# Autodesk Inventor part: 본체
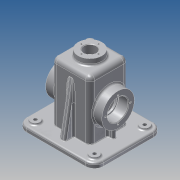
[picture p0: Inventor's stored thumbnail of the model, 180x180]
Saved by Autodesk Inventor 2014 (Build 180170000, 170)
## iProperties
Created: 2015-12
Part Number: 본체
Material: 알루미늄 6061
Document SubType Name: Modeling
Designer: Administrator
Density: 2.71 g/cm^3
Appearance: 알루미늄 - 평지
Mass: 957.91 g
Surface Area: 888.538 cm^2
Volume: 353.472 cm^3
Author: Administrator
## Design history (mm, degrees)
sketch "스케치1"
  geometry: L1 (-32.5, 32.5)-(32.5, 32.5); L2 (32.5, 32.5)-(32.5, -32.5); L3 (32.5, -32.5)-(-32.5, -32.5); L4 (-32.5, -32.5)-(-32.5, 32.5); 3 further points
  constraints: 8 end point, 2 midpoint, 2 parallel, 1 horizontal, 1 horizontal alignment, 1 perpendicular, 1 vertical alignment
  dimensions: "d0" = 65 distance of L1.start L1.end; "d1" = 65 distance of L1.end L2.end
extrude "돌출1" new body sketch "스케치1" distance "d2" = 100; taper "d3" = 0 deg
sketch "스케치2"
  geometry: L1 (-65, 57.5)-(65, 57.5); L2 (65, 57.5)-(65, -57.5); L3 (65, -57.5)-(-65, -57.5); L4 (-65, -57.5)-(-65, 57.5); 3 further points
  constraints: 8 end point, 2 midpoint, 2 parallel, 1 horizontal, 1 horizontal alignment, 1 perpendicular, 1 vertical alignment
  dimensions: "d4" = 130 distance of L2.end L3.end; "d5" = 115 distance of L1.end L2.end
extrude "돌출2" join sketch "스케치2" distance "d6" = 10; taper "d7" = 0 deg
sketch "스케치3"
  geometry: L1 (65, 57.5)-(-65, 57.5) reference; L2 (-65, 57.5)-(-65, -57.5) reference; L3 (-65, -57.5)-(65, -57.5) reference; L4 (65, -57.5)-(65, 57.5) reference; L5 (-60, 52.5)-(60, 52.5); L6 (60, 52.5)-(60, -52.5); L7 (60, -52.5)-(-60, -52.5); L8 (-60, -52.5)-(-60, 52.5); 1 further point
  constraints: 8 end point, 3 other
  dimensions: "d8" = 5 distance between parallel lines of L1 L5
extrude "돌출3" cut sketch "스케치3" distance "d9" = 2; taper "d10" = 0 deg
sketch "스케치4"
  geometry: C1 r 27.5 at (0, 45); 1 further point
  constraints: 1 centre point, 1 vertical alignment
  dimensions: "d11" = 55 diameter of C1; "d12" = 45 distance of point (0, 0) C1.centre
extrude "돌출4" join sketch "스케치4" stored distance "d13" = 95; taper "d14" = 0 deg
sketch "스케치5"
  geometry: C1 r 20 at (0, 0); 1 further point
  constraints: 1 centre point, 1 coincident
  dimensions: "d15" = 40 diameter of C1
extrude "돌출5" join sketch "스케치5" distance "d16" = 10; taper "d17" = 0 deg
sketch "스케치6"
  geometry: L1 (47.5, 0)-(31.327, 91.721); L2 (47.5, 0)-(158.49, 0); L3 (57.5, 0)-(57.5, -8) reference; L4 (47.5, 0)-(0, 0); L5 (31.327, 0)-(31.327, 91.721); L6 (0, 0)-(0, 53.654); L7 (-47.5, 0)-(-31.327, 91.721); L8 (-31.327, 0)-(-31.327, 91.721); L9 (-47.5, 0)-(0, 0)
  constraints: 16 end point, 3 symmetric about line, 2 point on line, 1 horizontal, 1 horizontal alignment, 1 parallel, 1 perpendicular
  dimensions: "d18" = 100 deg angle of L2 L1; "d19" = 10 distance from line of L1.start L3
sketch "스케치7"
  geometry: L1 (-42.5, 0)-(-42.5, 34.363); L2 (-42.5, 34.363)-(42.5, 34.363); L3 (42.5, 34.363)-(42.5, 0); L4 (42.5, 0)-(-42.5, 0); 2 further points
  constraints: 8 end point, 2 coincident, 2 parallel, 1 midpoint, 1 perpendicular, 1 vertical
  dimensions: "d20" = 85 distance of L3.end L1.start
extrude "돌출6" join sketch "스케치7" stored distance "d21" = 6; taper "d22" = 0 deg
hole "구멍1" diameter "d25" = 30; stored, may be unused: countersink angle "d29" = 90 deg, drill point angle "d31" = 0 deg; dims "d26" = 6, "d27" = 35, "d28" = 17, "d30" = 8, "d111" = 10, "d112" = 10
hole "구멍2" diameter "d34" = 30; stored, may be unused: countersink angle "d38" = 90 deg, drill point angle "d40" = 0 deg; dims "d35" = 6, "d36" = 35, "d37" = 17, "d39" = 8, "d113" = 10, "d114" = 10
sketch "스케치9"
  geometry: L1 (-27.5, 27.5)-(27.5, 27.5); L2 (27.5, 27.5)-(27.5, -27.5); L3 (27.5, -27.5)-(-27.5, -27.5); L4 (-27.5, -27.5)-(-27.5, 27.5); 3 further points
  constraints: 8 end point, 2 midpoint, 2 parallel, 1 horizontal, 1 horizontal alignment, 1 perpendicular, 1 vertical alignment
  dimensions: "d41" = 55 distance of L2.end L3.end; "d42" = 55 distance of L1.end L2.end
extrude "돌출7" cut sketch "스케치9" distance "d43" = 105; taper "d44" = 0 deg
feature "면 기울기1" dims angle "d110" = 5 deg
hole "구멍3" diameter "d47" = 21; stored, may be unused: countersink angle "d51" = 90 deg, drill point angle "d53" = 0 deg; dims "d45" = 10, "d46" = 10, "d48" = 6, "d49" = 32, "d50" = 17, "d52" = 20
extrude "돌출8" join sketch "스케치6" stored distance "d54" = 10; taper "d55" = 0 deg
sketch "스케치10"
  geometry: C1 r 7.5 at (-50, 42.5); C2 r 7.5 at (50, 42.5); C3 r 7.5 at (50, -42.5); C4 r 7.5 at (-50, -42.5); 5 further points
  constraints: 4 centre point, 4 coincident, 2 horizontal alignment, 2 vertical alignment
  dimensions: "d56" = 100 distance of point (50, 42.5) point (-50, 42.5); "d57" = 85 distance of point (50, -42.5) point (50, 42.5); "d58" = 50 horizontal distance of point (0, 0) point (-50, 42.5); "d59" = 42.5 vertical distance of point (0, 0) point (-50, 42.5); "d60" = 15 diameter of C1; "d61" = 15 diameter of C2; "d62" = 15 diameter of C3; "d63" = 15 diameter of C4
extrude "돌출9" join sketch "스케치10" distance "d64" = 3; taper "d65" = 0 deg
sketch "스케치11"
  geometry: C1 r 7.5 at (0, 0) reference; C2 r 7.5 at (0, 85) reference; C3 r 7.5 at (100, 85) reference; C4 r 7.5 at (100, 0) reference; 5 further points
  constraints: 4 coincident
hole "구멍4" sketch "스케치11" at (0, 85), (100, 85), (100, 0), (0, 0) diameter "d66" = 6; stored, may be unused: countersink angle "d70" = 90 deg, drill point angle "d72" = 0 deg; dims "d67" = 6, "d68" = 4, "d69" = 2, "d71" = 8
sketch "스케치12"
  geometry: C1 r 17.5 at (0, 0) reference; 5 further points
  constraints: 5 other
  dimensions: "d73" = 21 distance of C1.centre point (0, 21); "d76" = 360 deg dimension on C1.centre point (0, 21) (derived)
hole "구멍5" sketch "스케치12" at (0, 21), (-21, 0), (0, -21), (21, 0) diameter "d78" = 3.242; stored, may be unused: countersink angle "d82" = 90 deg, drill point angle "d84" = 118 deg; dims "d79" = 8, "d80" = 4, "d81" = 2, "d83" = 10
sketch "스케치13"
  geometry: C1 r 10.5 at (0, 0) reference; 4 further points
  constraints: 5 other
  dimensions: "d85" = 14.5 distance of point (0, 14.5) C1.centre; "d88" = 360 deg dimension on C1.centre point (0, 14.5) (derived)
hole "구멍6" sketch "스케치13" at (0, 14.5), (-14.5, 0), (0, -14.5), (14.5, 0) diameter "d90" = 2.459; stored, may be unused: countersink angle "d94" = 90 deg, drill point angle "d96" = 118 deg; dims "d91" = 7, "d92" = 4, "d93" = 2, "d95" = 9
chamfer "모따기1" distance "d97" = 1; stored, may be unused: second distance "d98" = 2, angle "d99" = 45 deg
fillet "모깎기1" dims "d100" = 0.3
fillet "모깎기2" dims "d101" = 15, "d102" = 8, "d115" = 10
fillet "모깎기3" dims "d103" = 3
fillet "모깎기4" dims "d104" = 1
fillet "모깎기5" dims "d105" = 3
sketch "스케치14"
  geometry: L1 (18, 4.5)-(18, 44.5) reference; L2 (0, 57)-(-91, 57) reference; 2 further points
  constraints: 1 other
  dimensions: "d106" = 26 distance from line of L1 point (-8, 24.5); "d107" = 32.5 distance from line of point (-8, 24.5) L2
feature "엠보싱1" sketch "스케치14" dims "d0" = 65, "d1" = 65, "d108" = 0.5, "d109" = 0
node "솔리드1"
mirror "대칭1"
node "투영된 루프1"
node "투영된 루프2"
node "투영된 루프3"
